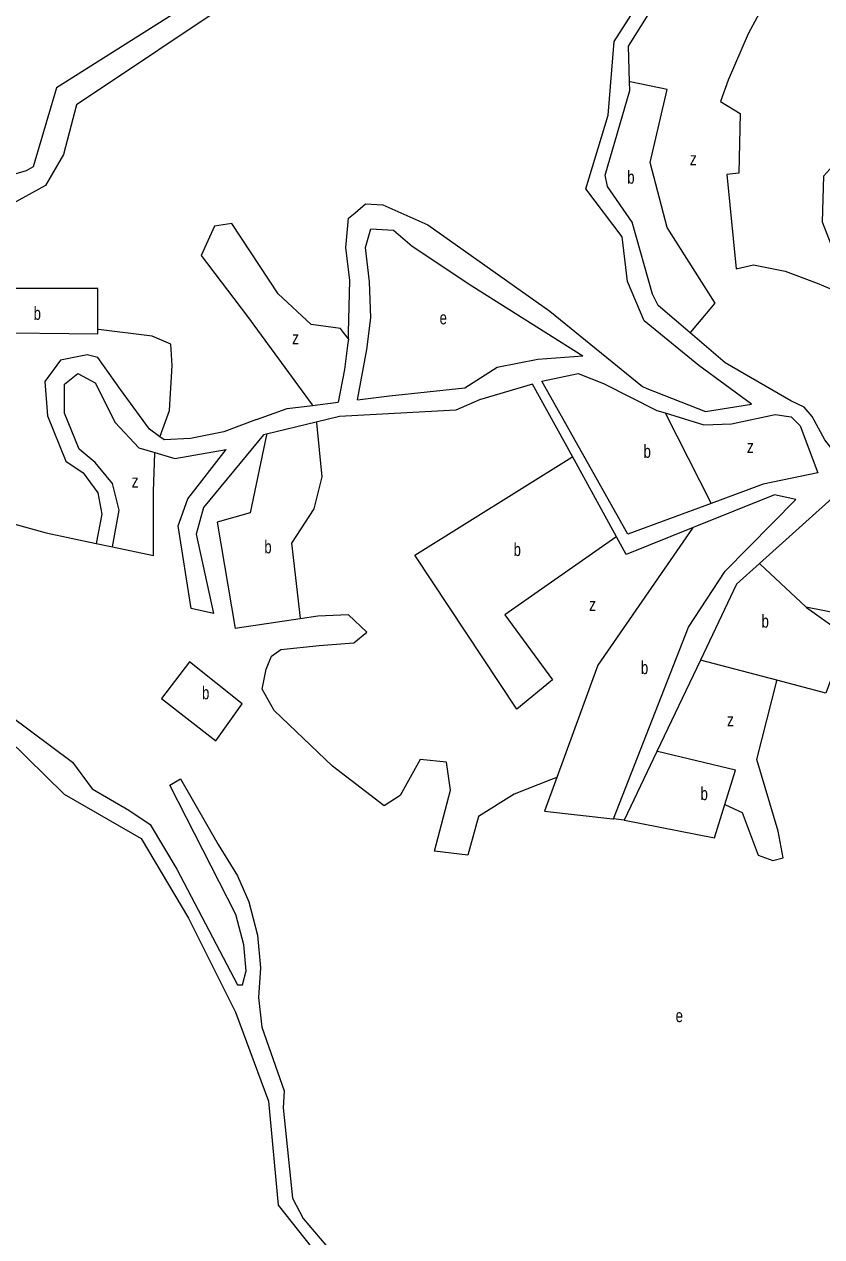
# Model space of a CAD drawing. Extents: x 639657 to 671642, y 222838 to 252123.
# Drawn here: x 643678 to 644289, y 240211 to 241140 of the extents above; entities that cross this region are included whole.
import ezdxf

# ---------------------------------------------------------------- set-up
doc = ezdxf.new("R2010")
doc.units = 0
doc.header["$LTSCALE"] = 4
doc.layers.add('1', color=7, linetype='Continuous', lineweight=13)
doc.layers.add('21', color=7, linetype='Continuous', lineweight=13)
doc.layers.add('7', color=7, linetype='Continuous')

msp = doc.modelspace()

# ---------------------------------------------------------------- linework, layer by layer
at = {"layer": '1'}
msp.add_line((643733.546, 240742.088), (643746.062, 240739.427), dxfattribs=at)
for points in [[(644151.807, 240862.194), (644155.25, 240860.61), (644200.16, 240843.07), (644235.38, 240848.71), (644195.17, 240878.28), (644153.23, 240912.57), (644140.3, 240942.62), (644136.38, 240976.98), (644108.61, 241013.66), (644125.7, 241070.17), (644130.12, 241126.44), (644191.6, 241222.11), (644243.49, 241278.68), (644298.66, 241290.79), (644342.05, 241283.56), (644401.35, 241272.06), (644412.44, 241317.39), (644439.66, 241351.8)], [(643830.7, 241288.32), (643912.86, 241208.99), (643913.74, 241201.26), (643898.52, 241183.84), (643843.79, 241162.06), (643718.29, 241077.88), (643708.47, 241039.85), (643694.76, 241016.21), (643664.08, 240999.41), (643552.89, 240964.43), (643524.16, 240936.04), (643527.83, 240924.45), (643530.482, 240885.854)], [(643891.388, 241209.643), (643892.9, 241204.45), (643890.12, 241198.86), (643884.11, 241194.98), (643837.32, 241176.01), (643703.02, 241090.96), (643685.29, 241030.58), (643679.93, 241027.35), (643593.2, 241002.51), (643530.11, 240975.99), (643511.88, 240955.56), (643509.14, 240928.07), (643515.169, 240879.957), (643524.37, 240806.54)], [(644142.03, 241095.662), (644141.3, 241123.02), (644169.626, 241168.319)], [(644188.516, 240903.29), (644163.95, 240924.19), (644159.64, 240932.99), (644143.88, 240988.16), (644125.15, 241015.4), (644123.42, 241024.2), (644142.21, 241088.88), (644142.03, 241095.662)], [(643926.651, 240898.615), (643926.765, 240903.616), (643927.667, 240943.323), (643924.62, 240968.726), (643926.651, 240991.08), (643931.73, 240995.144), (643939.855, 241002.257), (643953.058, 241001.241), (643987.589, 240985.999), (644081.027, 240919.953), (644151.807, 240862.194)], [(643933.606, 240852.069), (643940.87, 240890.486), (643943.917, 240914.872), (643942.901, 240942.307), (643939.855, 240968.726), (643943.917, 240982.951), (643961.183, 240981.935), (643975.401, 240969.742), (644021.105, 240939.259), (644106.18, 240885.79)], [(644369.439, 240806.395), (644363.66, 240807.47), (644328.44, 240805.05), (644312.12, 240805.02), (644299.44, 240811.23), (644291.69, 240821.31), (644281.99, 240839.33), (644275.76, 240846.41), (644265.65, 240851.33), (644215.35, 240880.46), (644188.516, 240903.29)], [(643926.651, 240898.615), (643925.999, 240893.616), (643923.605, 240875.244), (643918.925, 240850.235)], [(643782.19, 240823.784), (643774.307, 240829.52), (643751.964, 240860.003), (643734.698, 240884.389), (643726.573, 240886.421), (643706.26, 240882.357), (643694.073, 240866.099), (643696.104, 240839.681), (643710.323, 240805.133), (643723.526, 240795.988), (643734.698, 240780.747), (643737.745, 240764.489), (643733.546, 240742.088)], [(643933.606, 240852.069), (643958.11, 240855.13), (644015.87, 240861.24), (644040.54, 240876.96), (644071.67, 240883.24), (644106.18, 240885.79)], [(643746.062, 240739.427), (643750.948, 240767.538), (643745.87, 240787.86), (643732.667, 240804.117), (643720.479, 240814.278), (643709.307, 240841.713), (643709.307, 240864.067), (643719.464, 240872.196), (643732.667, 240865.083), (643747.901, 240834.6), (643766.182, 240815.294), (643778.503, 240811.642)], [(644074.82, 240866.23), (644102.62, 240872.12), (644122.17, 240864.63), (644163.01, 240843.87), (644169.235, 240841.942)], [(644204.477, 240772.641), (644140.61, 240749.12), (644074.82, 240866.23)], [(644098.206, 240808.509), (644067.74, 240864.06), (644027.05, 240852.02), (644009.02, 240844.05), (643919.91, 240839.18), (643902.039, 240834.878), (643863.986, 240825.716)], [(643856.34, 240836.93), (643879.74, 240845.34), (643899.179, 240847.768), (643918.925, 240850.235)], [(644169.235, 240841.942), (644198.89, 240832.76), (644220.15, 240833.65), (644253.64, 240840.79), (644265.67, 240838.88), (644272.56, 240832.02), (644286.15, 240796.17), (644244.28, 240787.3), (644204.477, 240772.641)], [(643856.34, 240836.93), (643831.183, 240827.488), (643805.792, 240822.407), (643785.479, 240821.391), (643782.19, 240823.784)], [(643863.986, 240825.716), (643861.51, 240825.12), (643815.64, 240769.43), (643810.09, 240749.01), (643823.29, 240688.26), (643806.1, 240692.1), (643796.34, 240755.44), (643803.61, 240776.06), (643832.951, 240813.952)], [(643778.503, 240811.642), (643793.604, 240807.166), (643832.951, 240813.952)], [(644190.685, 240754.169), (644139.37, 240733.45), (644131.897, 240747.075), (644098.206, 240808.509)], [(644366.922, 240794.455), (644362.17, 240795.44), (644302.28, 240781.38), (644241.437, 240726.53)], [(644129.8, 240531.12), (644187.12, 240677.89), (644215.18, 240720.89), (644269.43, 240775.74), (644253.1, 240779.37), (644190.685, 240754.169)], [(644241.437, 240726.53), (644224, 240710.81), (644196.249, 240652.654), (644162.848, 240582.658), (644137.75, 240530.06), (644129.8, 240531.12)], [(643622.36, 240634.67), (643708.83, 240549.98), (643767.95, 240516.14), (643804.13, 240455), (643840.11, 240383.11), (643865.56, 240314.85), (643872.78, 240235.19), (643934.11, 240157.76)], [(643667.07, 240610.48), (643715.45, 240574.47), (643730.3, 240554.1), (643758.46, 240537.82), (643774.8, 240526.68), (643795.26, 240492.56), (643841.79, 240403.94), (643845.44, 240403.95), (643848.22, 240414.69), (643846.47, 240434.45), (643840.42, 240457.85), (643790, 240556.98), (643797.94, 240561.72), (643826.8, 240511.52), (643841.66, 240487.49), (643850.49, 240467.53), (643856.98, 240441.98), (643859.38, 240417.07), (643857.7, 240394.3), (643860.31, 240371.54), (643877.57, 240322.82), (643876.74, 240309.72), (643883.94, 240240.58), (643892.12, 240224.91), (643944.19, 240163.79)]]:
    msp.add_lwpolyline(points, dxfattribs=at)
at = {"layer": '21'}
msp.add_line((643746.062, 240739.427), (643777.354, 240732.774), dxfattribs=at)
for points in [[(644250.13, 241164.834), (644232.864, 241132.318), (644217.63, 241096.755), (644211.536, 241080.497), (644226.77, 241071.352), (644225.755, 241025.628), (644216.614, 241024.612), (644223.723, 240952.468), (644236.926, 240955.517), (644261.301, 240950.436), (644285.676, 240941.291), (644310.052, 240931.13), (644317.161, 240939.259), (644314.114, 240952.468), (644296.848, 240969.742), (644289.739, 240988.032), (644290.755, 241023.596), (644299.895, 241033.757), (644314.114, 241028.676), (644341.536, 240999.209), (644364.861, 240964.333), (644385.719, 240933.147)], [(644188.516, 240903.29), (644188.932, 240903.79), (644207.473, 240926.05), (644170.911, 240983.968), (644157.708, 241033.757), (644170.911, 241089.642), (644142.529, 241095.558), (644142.03, 241095.662)], [(643926.651, 240898.615), (643922.902, 240903.616), (643920.558, 240906.743), (643898.214, 240909.792), (643872.823, 240933.162), (643837.276, 240987.015), (643824.073, 240984.983), (643813.917, 240962.629), (643849.464, 240915.888), (643898.814, 240848.268), (643899.179, 240847.768)], [(643734.698, 240905.854), (643734.698, 240937.226), (643647.557, 240937.226)], [(643645.323, 240903.695), (643734.698, 240902.679), (643734.698, 240905.854)], [(643782.19, 240823.784), (643782.374, 240824.284), (643789.542, 240843.745), (643791.573, 240878.293), (643790.557, 240894.55), (643776.339, 240900.647), (643735.198, 240905.791), (643734.698, 240905.854)], [(644169.235, 240841.942), (644169.489, 240841.443), (644204.223, 240773.141), (644204.477, 240772.641)], [(643902.039, 240834.878), (643902.09, 240834.378), (643906.339, 240792.94), (643900.245, 240768.554), (643882.979, 240742.135), (643889.596, 240684.76), (643889.654, 240684.26)], [(643863.986, 240825.716), (643863.882, 240825.216), (643851.495, 240765.505), (643826.104, 240758.393), (643839.841, 240676.992)], [(643545.2, 240805.28), (643545.7, 240805.388), (643568.135, 240810.214), (643600.635, 240795.988), (643643.292, 240764.489), (643695.089, 240750.264), (643733.546, 240742.088)], [(643777.354, 240732.774), (643777.354, 240781.763), (643778.484, 240811.142), (643778.503, 240811.642)], [(644131.897, 240747.075), (644131.397, 240746.725), (644046.496, 240687.267), (644083.058, 240637.478), (644055.636, 240615.123), (643977.433, 240732.991), (644097.706, 240808.196), (644098.206, 240808.509)], [(644190.685, 240754.169), (644190.339, 240753.669), (644117.59, 240648.655), (644086.378, 240562.784)], [(644241.437, 240726.53), (644241.937, 240726.064), (644277.043, 240693.363)], [(644277.043, 240693.363), (644277.543, 240693.008), (644308.527, 240671.009), (644292.277, 240627.317), (644254.901, 240637.179)], [(644277.043, 240693.363), (644365.403, 240676.089), (644390.793, 240664.912)], [(644086.378, 240562.784), (644081.379, 240560.848), (644053.605, 240550.092), (644026.183, 240532.818), (644018.058, 240503.352), (643992.668, 240506.4), (644004.855, 240553.141), (644001.808, 240574.479), (643981.496, 240576.511), (643966.261, 240549.076), (643954.073, 240540.947), (643914.464, 240571.43), (643869.776, 240614.106), (643860.636, 240630.364), (643863.683, 240645.605), (643867.745, 240655.766), (643874.855, 240660.847), (643904.308, 240663.896), (643930.714, 240665.928), (643940.871, 240674.057), (643926.652, 240687.266), (643903.292, 240686.25), (643889.654, 240684.26), (643839.841, 240676.992)], [(644254.901, 240637.179), (644201.249, 240651.335), (644196.249, 240652.654)], [(644214.925, 240541.947), (644215.425, 240541.72), (644228.293, 240535.867), (644240.48, 240503.352), (644251.652, 240499.288), (644259.777, 240501.32), (644255.715, 240521.642), (644239.465, 240576.511), (644254.774, 240636.679), (644254.901, 240637.179)], [(644214.925, 240541.947), (644223.215, 240568.383), (644163.348, 240582.54), (644162.848, 240582.658)], [(644086.378, 240562.784), (644076.965, 240536.884), (644129.3, 240531.175), (644129.8, 240531.12)], [(644137.75, 240530.06), (644138.25, 240529.962), (644206.965, 240516.562), (644214.925, 240541.947)]]:
    msp.add_lwpolyline(points, dxfattribs=at)
msp.add_lwpolyline([(643804.874, 240651.385), (643783.448, 240623.251), (643825.089, 240590.736), (643845.401, 240619.187)], close=True, dxfattribs=at)

# ---------------------------------------------------------------- texts
at = {"layer": '7'}
for s, width, p in [('z', 0.8, (644188.177, 241031.723)), ('b', 0.75, (644140.25, 241017.563)), ('b', 0.75, (643685.552, 240913.247)), ('e', 0.75, (643996.525, 240909.804)), ('z', 0.8, (643883.488, 240894.549)), ('b', 0.75, (644152.741, 240807.572)), ('z', 0.8, (644231.848, 240811.23)), ('z', 0.8, (643760.598, 240784.81)), ('b', 0.75, (643862.271, 240734.412)), ('b', 0.75, (644053.209, 240732.38)), ('z', 0.8, (644110.989, 240690.314)), ('b', 0.75, (644243.131, 240677.511)), ('b', 0.75, (644150.709, 240641.947)), ('b', 0.75, (643814.537, 240622.641)), ('z', 0.8, (644216.614, 240601.913)), ('b', 0.75, (644196.413, 240545.418)), ('e', 0.75, (644177.306, 240375.335))]:
    msp.add_text(s, height=10, dxfattribs=dict(at, width=width)).set_placement(p)

doc.saveas('drawing.dxf')
